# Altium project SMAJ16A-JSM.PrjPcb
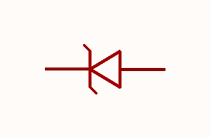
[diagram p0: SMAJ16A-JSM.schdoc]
1 sheet, 1 parts. Net scope: global (net labels, ports and power ports of the same name join across sheets).

## Sheet SMAJ16A-JSM.schdoc
size 127 x 101 mm

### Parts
D?  smaj16a-jsm  [SMA_L4.4-W2.6-LS5.1-RD]  (value not drawn)

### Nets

Not connected (* = marked no-connect by the designer): D? 1(C) 2(A)

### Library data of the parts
D? = smaj16a-jsm: 极性:单向;反向截止电压(Vrwm):16V;钳位电压:26V;峰值脉冲电流(Ipp):15.4A;峰值脉冲功率(Ppp):400W;击穿电压(VBR):19.7V;; Manufacturer: JSMSEMI(杰盛微); AddInBom: yes; ModelId: 21b4297b05f34eb58397f8f5cb4541ec; ModelTransform: 200.787,102.362,0,0,0,0,0,0,0; Polarity: 单向; Reverse Stand-Off Voltage (Vrwm): 16V; Clamping Voltage: 26V; Peak Pulse Current (Ipp): 15.4A; Peak Pulse Power Dissipation (Ppp): 400W; Voltage - Breakdown: 19.7V; Reverse Leakage Current (Ir): 1uA; Number of Channels: 单路; Type: TVS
